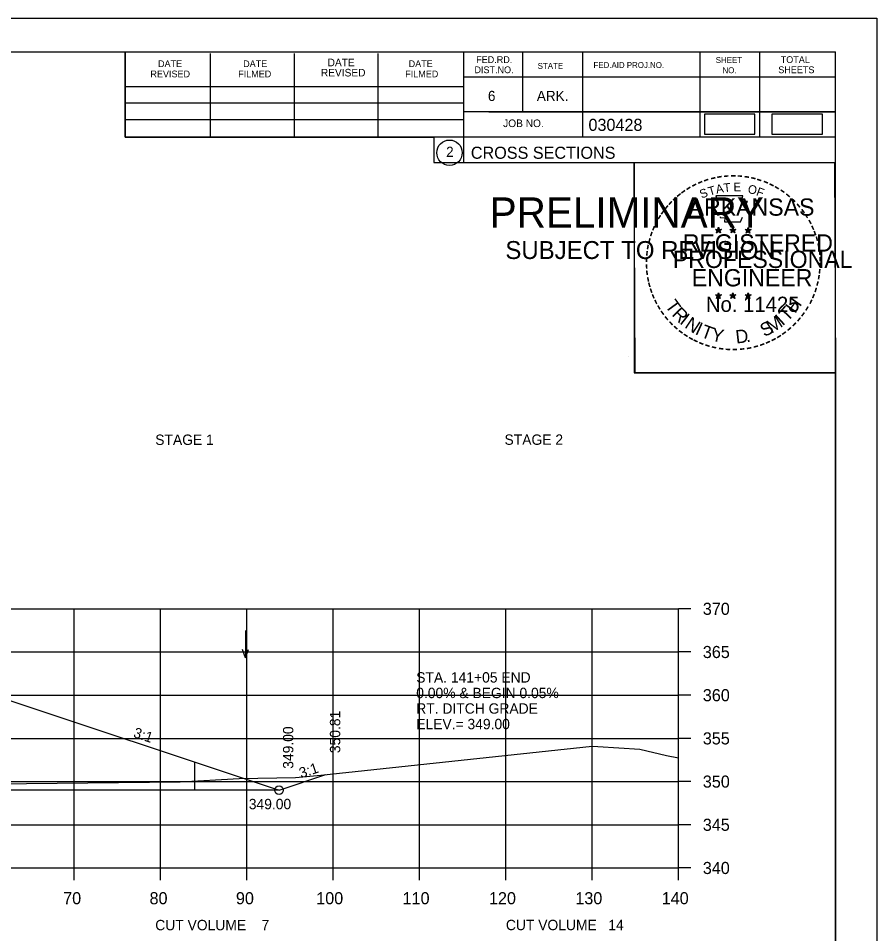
# Model space of a CAD drawing. Extents: x 1374859 to 1376773, y 382242 to 389804.
# Drawn here: x 1376198.1 to 1376297.5, y 385975.9 to 386081.8 of the extents above; entities that cross this region are included whole.
import ezdxf

# ---------------------------------------------------------------- set-up
doc = ezdxf.new("R2010")
doc.units = 0
for name, color, linetype in [('R_Axis', 7, 'Continuous'), ('R_Axis Annot', 7, 'Continuous'), ('R_Border', 7, 'Continuous'), ('R_Border PE', 7, 'Continuous'), ('R_Border Prem', 7, 'Continuous'), ('R_Detour Annot', 7, 'Continuous'), ('R_Drive', 7, 'Continuous'), ('R_Exist Surface', 7, 'Continuous'), ('R_Fin Surface', 7, 'Continuous'), ('R_Grid', 7, 'Continuous'), ('R_MOT', 7, 'Continuous'), ('R_No Plot', 7, 'Continuous'), ('R_Water', 7, 'Continuous'), ('R_Water Annot', 7, 'Continuous'), ('R_Xsect Elev', 7, 'Continuous'), ('R_Xsect Slope', 7, 'Continuous')]:
    doc.layers.add(name, color=color, linetype=linetype)

msp = doc.modelspace()

# ---------------------------------------------------------------- linework, layer by layer
at = {"layer": 'R_Axis'}
for p, q in [((1376274.57, 385983.47), (1376274.57, 386013.47)), ((1376275.97, 386013.47), (1376274.57, 386013.47)), ((1376275.97, 386008.47), (1376274.57, 386008.47)), ((1376275.97, 386003.47), (1376274.57, 386003.47)), ((1376275.97, 385998.47), (1376274.57, 385998.47)), ((1376275.97, 385993.47), (1376274.57, 385993.47)), ((1376275.97, 385988.47), (1376274.57, 385988.47)), ((1375994.57, 385983.47), (1376274.57, 385983.47)), ((1376204.57, 385982.07), (1376204.57, 385983.47)), ((1376214.57, 385982.07), (1376214.57, 385983.47)), ((1376224.57, 385982.07), (1376224.57, 385983.47)), ((1376234.57, 385982.07), (1376234.57, 385983.47)), ((1376244.57, 385982.07), (1376244.57, 385983.47)), ((1376254.57, 385982.07), (1376254.57, 385983.47)), ((1376264.57, 385982.07), (1376264.57, 385983.47)), ((1376274.57, 385982.07), (1376274.57, 385983.47)), ((1376275.97, 385983.47), (1376274.57, 385983.47))]:
    msp.add_line(p, q, dxfattribs=at)
at = {"layer": 'R_Border'}
for p, q in [((1375976.57, 386077.93), (1376292.75, 386077.93)), ((1376210.49, 386068.05), (1376210.49, 386077.93)), ((1376220.35, 386068.05), (1376220.35, 386077.73)), ((1376230.11, 386068.05), (1376230.11, 386077.73)), ((1376239.79, 386068.05), (1376239.79, 386077.73)), ((1376249.65, 386077.93), (1376249.65, 386065.13)), ((1376256.49, 386077.93), (1376256.49, 386070.99)), ((1376263.43, 386077.93), (1376263.43, 386068.05)), ((1376277.01, 386077.93), (1376277.01, 386068.05)), ((1376283.95, 386077.93), (1376283.95, 386068.05)), ((1376292.75, 385872.47), (1376292.75, 386077.93)), ((1376292.75, 386074.99), (1376249.65, 386074.99)), ((1376292.75, 386075.01), (1376292.75, 386075.01)), ((1376210.49, 386073.91), (1376249.65, 386073.91)), ((1376210.49, 386072.05), (1376249.65, 386072.05)), ((1376292.75, 386070.99), (1376249.65, 386070.99)), ((1376252.61, 386070.99), (1376292.75, 386070.99)), ((1376210.49, 386068.05), (1376210.49, 386070.11)), ((1376210.49, 386070.11), (1376249.65, 386070.11)), ((1376292.75, 386068.05), (1376210.49, 386068.05)), ((1376249.65, 386065.13), (1376292.75, 386065.13))]:
    msp.add_line(p, q, dxfattribs=at)
msp.add_circle((1376248.04, 386066.26), 1.47, dxfattribs=at)
at = {"layer": 'R_Border PE'}
for p, q in [((1376278.84, 386057.38), (1376279.18, 386057.27)), ((1376278.84, 386057.38), (1376279.09, 386057.34)), ((1376278.84, 386057.38), (1376279.07, 386057.26)), ((1376278.97, 386056.97), (1376279.18, 386057.27)), ((1376278.97, 386056.97), (1376279.09, 386057.22)), ((1376278.97, 386056.97), (1376279.18, 386057.19)), ((1376279.18, 386057.64), (1376279.14, 386057.38)), ((1376279.18, 386057.27), (1376279.18, 386057.64)), ((1376279.18, 386057.64), (1376279.23, 386057.39)), ((1376279.53, 386057.38), (1376279.18, 386057.27)), ((1376279.4, 386056.97), (1376279.18, 386057.27)), ((1376279.4, 386056.97), (1376279.18, 386057.19)), ((1376279.53, 386057.38), (1376279.25, 386057.33)), ((1376279.4, 386056.97), (1376279.26, 386057.26)), ((1376279.53, 386057.38), (1376279.33, 386057.28)), ((1376280.51, 386057.38), (1376280.85, 386057.27)), ((1376280.51, 386057.38), (1376280.76, 386057.34)), ((1376280.51, 386057.38), (1376280.74, 386057.26)), ((1376280.64, 386056.97), (1376280.85, 386057.27)), ((1376280.64, 386056.97), (1376280.76, 386057.22)), ((1376280.64, 386056.97), (1376280.85, 386057.19)), ((1376280.85, 386057.64), (1376280.81, 386057.38)), ((1376280.85, 386057.27), (1376280.85, 386057.64)), ((1376280.85, 386057.64), (1376280.9, 386057.39)), ((1376281.2, 386057.38), (1376280.85, 386057.27)), ((1376281.07, 386056.97), (1376280.85, 386057.27)), ((1376281.07, 386056.97), (1376280.85, 386057.19)), ((1376281.2, 386057.38), (1376280.92, 386057.33)), ((1376281.07, 386056.97), (1376280.93, 386057.26)), ((1376281.2, 386057.38), (1376281, 386057.28)), ((1376282.27, 386057.37), (1376282.62, 386057.26)), ((1376282.27, 386057.37), (1376282.52, 386057.32)), ((1376282.27, 386057.37), (1376282.51, 386057.25)), ((1376282.4, 386056.96), (1376282.62, 386057.26)), ((1376282.4, 386056.96), (1376282.53, 386057.21)), ((1376282.4, 386056.96), (1376282.62, 386057.18)), ((1376282.62, 386057.62), (1376282.58, 386057.37)), ((1376282.62, 386057.26), (1376282.62, 386057.62)), ((1376282.62, 386057.62), (1376282.67, 386057.37)), ((1376282.97, 386057.37), (1376282.62, 386057.26)), ((1376282.83, 386056.96), (1376282.62, 386057.26)), ((1376282.83, 386056.96), (1376282.62, 386057.18)), ((1376282.97, 386057.37), (1376282.68, 386057.32)), ((1376282.83, 386056.96), (1376282.69, 386057.25)), ((1376282.97, 386057.37), (1376282.76, 386057.27)), ((1376278.83, 386049.81), (1376279.18, 386049.7)), ((1376278.83, 386049.81), (1376279.08, 386049.76)), ((1376278.83, 386049.81), (1376279.07, 386049.69)), ((1376278.96, 386049.4), (1376279.18, 386049.7)), ((1376278.96, 386049.4), (1376279.09, 386049.64)), ((1376278.96, 386049.4), (1376279.18, 386049.62)), ((1376279.18, 386050.06), (1376279.14, 386049.81)), ((1376279.18, 386049.7), (1376279.18, 386050.06)), ((1376279.18, 386050.06), (1376279.23, 386049.81)), ((1376279.53, 386049.81), (1376279.18, 386049.7)), ((1376279.39, 386049.4), (1376279.18, 386049.7)), ((1376279.39, 386049.4), (1376279.18, 386049.61)), ((1376279.53, 386049.81), (1376279.24, 386049.76)), ((1376279.39, 386049.4), (1376279.26, 386049.69)), ((1376279.53, 386049.81), (1376279.32, 386049.71)), ((1376280.5, 386049.81), (1376280.85, 386049.7)), ((1376280.5, 386049.81), (1376280.75, 386049.76)), ((1376280.5, 386049.81), (1376280.74, 386049.69)), ((1376280.63, 386049.4), (1376280.85, 386049.7)), ((1376280.63, 386049.4), (1376280.76, 386049.64)), ((1376280.63, 386049.4), (1376280.85, 386049.62)), ((1376280.85, 386050.06), (1376280.81, 386049.81)), ((1376280.85, 386049.7), (1376280.85, 386050.06)), ((1376280.85, 386050.06), (1376280.9, 386049.81)), ((1376281.2, 386049.81), (1376280.85, 386049.7)), ((1376281.06, 386049.4), (1376280.85, 386049.7)), ((1376281.06, 386049.4), (1376280.85, 386049.61)), ((1376281.2, 386049.81), (1376280.91, 386049.76)), ((1376281.06, 386049.4), (1376280.93, 386049.69)), ((1376281.2, 386049.81), (1376280.99, 386049.71)), ((1376282.27, 386049.8), (1376282.62, 386049.69)), ((1376282.27, 386049.8), (1376282.52, 386049.75)), ((1376282.27, 386049.8), (1376282.5, 386049.68)), ((1376282.4, 386049.39), (1376282.62, 386049.69)), ((1376282.4, 386049.39), (1376282.53, 386049.63)), ((1376282.4, 386049.39), (1376282.61, 386049.61)), ((1376282.62, 386050.05), (1376282.58, 386049.8)), ((1376282.83, 386049.39), (1376282.61, 386049.6)), ((1376282.62, 386049.69), (1376282.62, 386050.05)), ((1376282.62, 386050.05), (1376282.67, 386049.8)), ((1376282.96, 386049.8), (1376282.62, 386049.69)), ((1376282.83, 386049.39), (1376282.62, 386049.69)), ((1376282.96, 386049.8), (1376282.68, 386049.75)), ((1376282.83, 386049.39), (1376282.69, 386049.68)), ((1376282.96, 386049.8), (1376282.76, 386049.7))]:
    msp.add_line(p, q, dxfattribs=at)
for points in [[(1376278.88, 386061.26), (1376279.15, 386060.43)], [(1376282.39, 386060.34), (1376282.53, 386060.62), (1376281.84, 386060.6), (1376281.99, 386061.26), (1376278.88, 386061.26)], [(1376279.37, 386058.84), (1376279.37, 386058.75), (1376279.93, 386058.73), (1376279.88, 386058.26), (1376281.75, 386058.26), (1376281.95, 386058.79)], [(1376279.18, 386057.64), (1376279.4, 386056.97), (1376278.84, 386057.38), (1376279.53, 386057.38), (1376278.97, 386056.97), (1376279.18, 386057.64)], [(1376280.85, 386057.64), (1376281.07, 386056.97), (1376280.51, 386057.38), (1376281.2, 386057.38), (1376280.64, 386056.97), (1376280.85, 386057.64)], [(1376282.62, 386057.62), (1376282.83, 386056.96), (1376282.27, 386057.37), (1376282.97, 386057.37), (1376282.4, 386056.96), (1376282.62, 386057.62)], [(1376279.18, 386050.06), (1376279.39, 386049.4), (1376278.83, 386049.81), (1376279.53, 386049.81), (1376278.96, 386049.4), (1376279.18, 386050.06)], [(1376280.85, 386050.06), (1376281.06, 386049.4), (1376280.5, 386049.81), (1376281.2, 386049.81), (1376280.63, 386049.4), (1376280.85, 386050.06)], [(1376282.62, 386050.05), (1376282.83, 386049.39), (1376282.27, 386049.8), (1376282.96, 386049.8), (1376282.4, 386049.39), (1376282.62, 386050.05)]]:
    msp.add_lwpolyline(points, dxfattribs=at)
for centre, radius in [((1376279.18, 386057.27), 0.172), ((1376279.18, 386057.27), 0.145), ((1376279.18, 386057.27), 0.116), ((1376279.18, 386057.27), 0.0991), ((1376279.18, 386057.27), 0.0747), ((1376279.18, 386057.27), 0.0495), ((1376279.18, 386057.27), 0.0296), ((1376280.85, 386057.27), 0.172), ((1376280.85, 386057.27), 0.145), ((1376280.85, 386057.27), 0.116), ((1376280.85, 386057.27), 0.0991), ((1376280.85, 386057.27), 0.0747), ((1376280.85, 386057.27), 0.0495), ((1376280.85, 386057.27), 0.0296), ((1376282.62, 386057.26), 0.172), ((1376282.62, 386057.26), 0.145), ((1376282.62, 386057.26), 0.116), ((1376282.62, 386057.26), 0.0991), ((1376282.62, 386057.26), 0.0747), ((1376282.62, 386057.26), 0.0495), ((1376282.62, 386057.26), 0.0296), ((1376279.18, 386049.7), 0.172), ((1376279.18, 386049.7), 0.145), ((1376279.18, 386049.7), 0.116), ((1376279.18, 386049.7), 0.0991), ((1376279.18, 386049.7), 0.0747), ((1376279.18, 386049.7), 0.0495), ((1376279.18, 386049.7), 0.0296), ((1376280.85, 386049.7), 0.172), ((1376280.85, 386049.7), 0.145), ((1376280.85, 386049.7), 0.116), ((1376280.85, 386049.7), 0.0991), ((1376280.85, 386049.7), 0.0747), ((1376280.85, 386049.7), 0.0495), ((1376280.85, 386049.7), 0.0296), ((1376282.62, 386049.69), 0.172), ((1376282.62, 386049.69), 0.145), ((1376282.62, 386049.69), 0.116), ((1376282.62, 386049.69), 0.0991), ((1376282.62, 386049.69), 0.0747), ((1376282.62, 386049.69), 0.0495), ((1376282.62, 386049.69), 0.0296)]:
    msp.add_circle(centre, radius, dxfattribs=at)
at = {"layer": 'R_Drive'}
msp.add_lwpolyline([(1376277.58, 386068.4), (1376283.41, 386068.4), (1376283.41, 386070.71), (1376277.58, 386070.71)], close=True, dxfattribs=at)
at = {"layer": 'R_Exist Surface'}
msp.add_lwpolyline([(1375994.57, 385995.62), (1376002.74, 385995.46), (1376014.19, 385995.28), (1376019.58, 385995.19), (1376022.61, 385995.09), (1376030.3, 385995), (1376035.21, 385994.97), (1376039.19, 385995.14), (1376047.5, 385994.94), (1376089.39, 385993.87), (1376097.16, 385993.45), (1376139.11, 385992.24), (1376144.38, 385992.36), (1376174.09, 385992.98), (1376216.85, 385993.46), (1376223.69, 385993.82), (1376230.2, 385993.93), (1376233.13, 385994.21), (1376264.56, 385997.56), (1376265.22, 385997.54), (1376270.08, 385997.22), (1376273.18, 385996.49), (1376274.57, 385996.2)], dxfattribs=at)
at = {"layer": 'R_Fin Surface'}
msp.add_lwpolyline([(1376027.15, 385995.04), (1376037.87, 385991.47), (1376075.09, 386003.87), (1376089.65, 386006.3), (1376097.09, 386007.54), (1376105.09, 386007.86), (1376134.59, 386008.45), (1376164.09, 386007.86), (1376172.09, 386007.54), (1376179.52, 386006.3), (1376194.09, 386003.87), (1376228.3, 385992.47), (1376233.74, 385994.28)], dxfattribs=at)
at = {"layer": 'R_Grid'}
for p, q in [((1375994.57, 386013.47), (1376274.57, 386013.47)), ((1376204.57, 385983.47), (1376204.57, 386013.47)), ((1376214.57, 385983.47), (1376214.57, 386013.47)), ((1376224.57, 385983.47), (1376224.57, 386013.47)), ((1376234.57, 385983.47), (1376234.57, 386013.47)), ((1376244.57, 385983.47), (1376244.57, 386013.47)), ((1376254.57, 385983.47), (1376254.57, 386013.47)), ((1376264.57, 385983.47), (1376264.57, 386013.47)), ((1376274.57, 385983.47), (1376274.57, 386013.47)), ((1375994.57, 386008.47), (1376274.57, 386008.47)), ((1375994.57, 386003.47), (1376274.57, 386003.47)), ((1375994.57, 385998.47), (1376274.57, 385998.47)), ((1375994.57, 385993.47), (1376274.57, 385993.47)), ((1375994.57, 385988.47), (1376274.57, 385988.47)), ((1375994.57, 385983.47), (1376274.57, 385983.47))]:
    msp.add_line(p, q, dxfattribs=at)
at = {"layer": 'R_MOT'}
msp.add_lwpolyline([(1376285.38, 386068.41), (1376291.21, 386068.41), (1376291.21, 386070.72), (1376285.38, 386070.72)], close=True, dxfattribs=at)
at = {"layer": 'R_No Plot'}
for p, q in [((1375964.17, 386081.82), (1376297.5, 386081.82)), ((1376268.78, 386042.67), (1376268.78, 386042.67))]:
    msp.add_line(p, q, dxfattribs=at)
for points in [[(1375964.16, 386081.82), (1376297.5, 386081.82), (1376297.5, 385868.48), (1375964.16, 385868.48)], [(1376210.49, 386077.93), (1376210.49, 386068.05), (1376246.22, 386068.05), (1376246.22, 386065.13), (1376269.42, 386065.13), (1376269.42, 386040.79), (1376292.75, 386040.79), (1376292.75, 385872.47), (1375976.57, 385872.47), (1375976.57, 386077.93)], [(1376269.42, 386065.13), (1376292.63, 386065.13), (1376292.75, 386040.79), (1376269.54, 386040.79)]]:
    msp.add_lwpolyline(points, close=True, dxfattribs=at)
msp.add_circle((1376228.3, 385992.47), 0.5, dxfattribs=at)
at = {"layer": 'R_Water'}
msp.add_line((1376218.52, 385995.73), (1376218.53, 385992.47), dxfattribs=at)
msp.add_lwpolyline([(1376228.32, 385992.47), (1376196.03, 385992.47), (1376070.32, 385991.46), (1376037.82, 385991.46)], dxfattribs=at)
at = {"layer": 'R_Water Annot'}
for p, q in [((1376224.41, 386010.94), (1376224.41, 386007.8)), ((1376224.41, 386007.8), (1376224.06, 386008.76)), ((1376224.41, 386007.8), (1376224.76, 386008.76))]:
    msp.add_line(p, q, dxfattribs=at)

# ---------------------------------------------------------------- texts
at = {"layer": 'R_Axis Annot'}
for s, p in [('STAGE 1', (1376213.97, 386032.44)), ('STAGE 2', (1376254.41, 386032.45))]:
    msp.add_text(s, height=1.2, rotation=360, dxfattribs=at).set_placement(p)
for s, height, p in [('370', 1.4, (1376277.37, 386012.77)), ('365', 1.4, (1376277.37, 386007.77)), ('360', 1.4, (1376277.37, 386002.77)), ('355', 1.4, (1376277.37, 385997.77)), ('350', 1.4, (1376277.37, 385992.77)), ('345', 1.4, (1376277.37, 385987.77)), ('340', 1.4, (1376277.37, 385982.77)), ('70', 1.4, (1376203.31, 385979.27)), ('80', 1.4, (1376213.31, 385979.27)), ('90', 1.4, (1376223.31, 385979.27)), ('100', 1.4, (1376232.61, 385979.27)), ('110', 1.4, (1376242.61, 385979.27)), ('120', 1.4, (1376252.61, 385979.27)), ('130', 1.4, (1376262.61, 385979.27)), ('140', 1.4, (1376272.61, 385979.27)), ('CUT VOLUME    7', 1.2, (1376213.97, 385976.26)), ('CUT VOLUME   14', 1.2, (1376254.57, 385976.27))]:
    msp.add_text(s, height=height, dxfattribs=at).set_placement(p)
at = {"layer": 'R_Border'}
for s, height, p in [('FED.RD.', 0.782, (1376251.13, 386076.65)), ('SHEET', 0.684, (1376278.87, 386076.65)), ('TOTAL', 0.782, (1376286.39, 386076.65)), ('DATE', 0.782, (1376214.29, 386076.17)), ('DATE', 0.782, (1376224.15, 386076.17)), ('DATE', 0.879, (1376233.93, 386076.27)), ('DATE', 0.782, (1376243.31, 386076.17)), ('DIST.NO.', 0.782, (1376250.93, 386075.47)), ('STATE', 0.684, (1376258.25, 386075.97)), ('FED.AID PROJ.NO.', 0.684, (1376264.71, 386076.07)), ('NO.', 0.684, (1376279.65, 386075.47)), ('SHEETS', 0.782, (1376286.11, 386075.47)), ('REVISED', 0.782, (1376213.41, 386074.99)), ('FILMED', 0.782, (1376223.57, 386074.99)), ('REVISED', 0.879, (1376233.15, 386075.09)), ('FILMED', 0.782, (1376242.91, 386074.99)), ('6', 1.17, (1376252.49, 386072.25)), ('ARK.', 1.172, (1376258.15, 386072.25)), ('JOB NO.', 0.879, (1376254.25, 386069.23)), ('030428', 1.4, (1376264.13, 386068.79)), ('2', 1.17, (1376247.65, 386065.78)), ('CROSS SECTIONS', 1.4, (1376250.51, 386065.56))]:
    msp.add_text(s, height=height, rotation=360, dxfattribs=at).set_placement(p)
at = {"layer": 'R_Border PE'}
for s, height, rotation, p in [('-', 1.6, 13.6301, (1376278.37, 386062.63)), ('-', 1.6, 10.2193, (1376279.05, 386062.79)), ('-', 1.6, 5.8968, (1376279.78, 386062.9)), ('-', 1.6, 0.1862, (1376280.55, 386062.97)), ('-', 1.6, 357.743, (1376281.28, 386062.96)), ('-', 1.6, 352.1617, (1376282.02, 386062.9)), ('-', 1.6, 347.2049, (1376282.74, 386062.79)), ('-', 1.6, 34.0636, (1376275.76, 386061.43)), ('-', 1.6, 28.7918, (1376276.36, 386061.8)), ('-', 1.6, 24.3072, (1376276.99, 386062.12)), ('-', 1.6, 19.1761, (1376277.62, 386062.39)), ('T', 1, 16.4036, (1376278.15, 386061.27)), ('A', 1, 11.2132, (1376278.97, 386061.52)), ('T', 1, 6.0228, (1376279.82, 386061.69)), ('E', 1, 0.8323, (1376280.93, 386061.8)), ('O', 1, 350.4515, (1376282.53, 386061.59)), ('-', 1.6, 342.3362, (1376283.37, 386062.63)), ('-', 1.6, 337.8551, (1376284.11, 386062.41)), ('-', 1.6, 334.1211, (1376284.74, 386062.14)), ('-', 1.6, 329.6409, (1376285.32, 386061.86)), ('-', 1.6, 38.9507, (1376274.71, 386060.66)), ('-', 1.6, 36.2317, (1376275.18, 386061.04)), ('S', 1, 21.594, (1376277.23, 386060.94)), ('F', 1, 340.0707, (1376283.48, 386061.36)), ('-', 1.6, 325.8627, (1376285.96, 386061.5)), ('-', 1.6, 320.5297, (1376286.57, 386061.07)), ('-', 1.6, 50.6142, (1376273.42, 386059.28)), ('-', 1.6, 48.423, (1376273.83, 386059.76)), ('-', 1.6, 42.9622, (1376274.27, 386060.24)), ('ARKANSAS', 2, 360, (1376275.73, 386058.97)), ('-', 1.6, 315.5786, (1376287.17, 386060.58)), ('-', 1.6, 309.8797, (1376287.74, 386060.03)), ('-', 1.6, 54.2325, (1376273.01, 386058.71)), ('-', 1.6, 306.6522, (1376288.27, 386059.43)), ('-', 1.6, 62.8713, (1376272.37, 386057.57)), ('-', 1.6, 58.0706, (1376272.68, 386058.18)), ('-', 1.4, 303.6753, (1376288.75, 386058.86)), ('-', 1.6, 299.6684, (1376289.07, 386058.25)), ('-', 1.6, 72.3945, (1376271.89, 386056.33)), ('-', 1.6, 67.7743, (1376272.11, 386056.96)), ('DWB', 0.01, 360, (1376279.17, 386057.26)), ('DWB', 0.01, 360, (1376280.84, 386057.26)), ('DWB', 0.01, 360, (1376282.61, 386057.25)), ('-', 1.6, 294.6628, (1376289.39, 386057.64)), ('-', 1.6, 290.5728, (1376289.65, 386057.07)), ('-', 1.6, 75.461, (1376271.7, 386055.61)), ('REGISTERED', 2, 360, (1376275.05, 386054.82)), ('-', 1.6, 285.1233, (1376289.89, 386056.49)), ('-', 1.6, 81.2013, (1376271.56, 386054.9)), ('PROFESSIONAL', 2, 360, (1376273.9, 386052.92)), ('-', 1.6, 280.5493, (1376290.09, 386055.74)), ('-', 1.6, 276.5962, (1376290.25, 386054.98)), ('-', 1.6, 89.0622, (1376271.46, 386053.51)), ('-', 1.6, 85.1863, (1376271.49, 386054.21)), ('-', 1.6, 274.3301, (1376290.31, 386054.25)), ('-', 1.6, 94.1959, (1376271.5, 386052.78)), ('ENGINEER', 2, 360, (1376276.09, 386050.79)), ('-', 1.6, 263.5172, (1376290.32, 386052.96)), ('-', 1.6, 269.9407, (1376290.34, 386053.62)), ('-', 1.6, 98.9479, (1376271.57, 386052.12)), ('-', 1.6, 101.7149, (1376271.71, 386051.38)), ('-', 1.6, 260.9953, (1376290.25, 386052.3)), ('-', 1.6, 105.4578, (1376271.87, 386050.79)), ('-', 1.6, 255.7626, (1376290.14, 386051.62)), ('-', 1.6, 109.0874, (1376272.08, 386050.16)), ('-', 1.6, 114.0643, (1376272.34, 386049.56)), ('No. 11425', 1.757, 360, (1376277.72, 386047.84)), ('DWB', 0.01, 360, (1376279.17, 386049.69)), ('DWB', 0.01, 360, (1376280.84, 386049.69)), ('DWB', 0.01, 360, (1376282.6, 386049.68)), ('-', 1.6, 247.8887, (1376289.74, 386050.23)), ('-', 1.6, 252.8681, (1376289.96, 386050.9)), ('-', 1.6, 115.7289, (1376272.64, 386048.94)), ('-', 1.6, 120.4471, (1376273, 386048.36)), ('T', 1.54, 306.0406, (1376272.94, 386048.54)), ('T', 1.54, 46.6444, (1376287.17, 386046.63)), ('H', 1.54, 54.6088, (1376288.06, 386047.57)), ('-', 1.6, 244.6197, (1376289.48, 386049.6)), ('-', 1.6, 125.8934, (1376273.4, 386047.8)), ('R', 1.54, 314.005, (1376273.7, 386047.49)), ('I', 1.54, 321.9694, (1376274.6, 386046.56)), ('I', 1.54, 42.1136, (1376286.61, 386046.15)), ('-', 1.6, 233.8452, (1376288.68, 386048.2)), ('-', 1.6, 239.0712, (1376289.08, 386048.85)), ('-', 1.6, 130.7181, (1376273.86, 386047.24)), ('-', 1.6, 134.2238, (1376274.38, 386046.7)), ('N', 1.54, 326.5002, (1376275.17, 386046.08)), ('I', 1.54, 335.3603, (1376276.38, 386045.3)), ('S', 1.54, 26.9312, (1376284.49, 386044.9)), ('M', 1.54, 32.6563, (1376285.32, 386045.3)), ('-', 1.6, 225.7653, (1376287.77, 386047.07)), ('-', 1.6, 231.2538, (1376288.25, 386047.63)), ('-', 1.6, 138.9338, (1376274.91, 386046.24)), ('-', 1.6, 144.6463, (1376275.46, 386045.83)), ('T', 1.54, 339.8912, (1376277.04, 386044.97)), ('Y', 1.54, 347.8556, (1376278.26, 386044.53)), ('D', 1.54, 6.3969, (1376281.24, 386044.17)), ('-', 1.6, 215.7363, (1376286.7, 386046.09)), ('-', 1.6, 221.0851, (1376287.25, 386046.56)), ('-', 1.6, 148.0898, (1376276.02, 386045.46)), ('-', 1.6, 151.5704, (1376276.6, 386045.13)), ('-', 1.6, 154.6002, (1376277.12, 386044.89)), ('-', 1.6, 158.5612, (1376277.75, 386044.63)), ('.', 1.54, 13.7642, (1376282.43, 386044.29)), ('-', 1.6, 204.2516, (1376284.98, 386045.03)), ('-', 1.6, 207.3568, (1376285.61, 386045.35)), ('-', 1.6, 212.2491, (1376286.17, 386045.7)), ('-', 1.6, 162.7983, (1376278.43, 386044.42)), ('-', 1.6, 167.5555, (1376279.15, 386044.26)), ('-', 1.6, 173.1155, (1376279.92, 386044.15)), ('-', 1.6, 176.5183, (1376280.67, 386044.09)), ('-', 1.6, 181.5918, (1376281.41, 386044.11)), ('-', 1.6, 185.8167, (1376282.22, 386044.19)), ('-', 1.6, 191.2858, (1376282.96, 386044.32)), ('-', 1.6, 195.4743, (1376283.69, 386044.52)), ('-', 1.6, 200.7184, (1376284.36, 386044.76))]:
    msp.add_text(s, height=height, rotation=rotation, dxfattribs=at).set_placement(p)
at = {"layer": 'R_Border Prem'}
for s, height, p in [('PRELIMINARY', 3.5, (1376252.7, 386057.59)), ('DWB', 0.01, (1376253.45, 386059.44)), ('SUBJECT TO REVISION', 2.0751, (1376254.51, 386053.96))]:
    msp.add_text(s, height=height, rotation=360, dxfattribs=at).set_placement(p)
at = {"layer": 'R_Detour Annot'}
for s, p in [('STA. 141+05 END', (1376244.19, 386004.93)), ('0.00% & BEGIN 0.05%', (1376244.19, 386003.13)), ('RT. DITCH GRADE', (1376244.19, 386001.33)), ('ELEV.= 349.00', (1376244.19, 385999.53))]:
    msp.add_text(s, height=1.2, dxfattribs=at).set_placement(p)
at = {"layer": 'R_Xsect Elev'}
for s, p in [('350.81', (1376235.39, 385996.76)), ('349.00', (1376229.96, 385994.95))]:
    msp.add_text(s, height=1.2, rotation=90, dxfattribs=at).set_placement(p)
msp.add_text('349.00', height=1.2, dxfattribs=at).set_placement((1376224.8, 385990.27))
at = {"layer": 'R_Xsect Slope'}
for rotation, p in [(341.5651, (1376211.35, 385998.64)), (18.4349, (1376230.86, 385993.85))]:
    msp.add_text('3:1', height=1.2, rotation=rotation, dxfattribs=at).set_placement(p)

doc.saveas('drawing.dxf')
